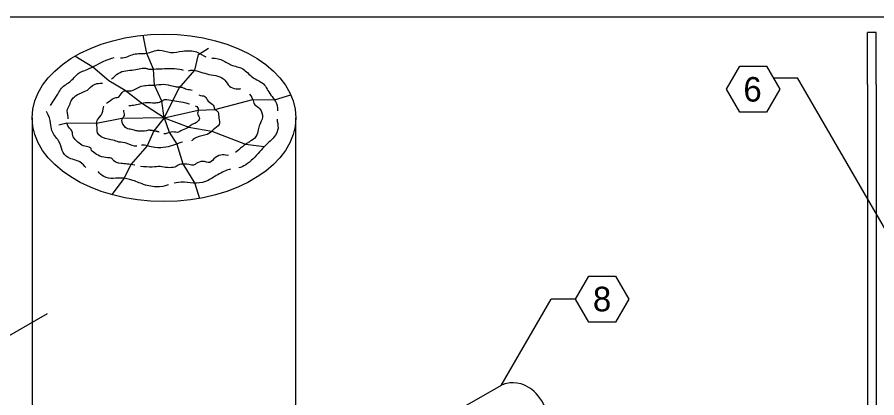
# Model space of a CAD drawing. Extents: x 99862 to 103151, y 100000 to 105076.
# Drawn here: x 100805 to 101365, y 104827 to 105076 of the extents above; entities that cross this region are included whole.
import ezdxf

# ---------------------------------------------------------------- set-up
doc = ezdxf.new("R2010")
doc.units = 0
for name, color, linetype in [('Level 1', 7, 'Continuous'), ('Level 13', 7, 'Continuous'), ('Level 15', 7, 'Continuous'), ('Level 16', 7, 'Continuous'), ('Level 20', 7, 'Continuous'), ('Level 31', 7, 'Continuous'), ('Level 41', 7, 'Continuous')]:
    doc.layers.add(name, color=color, linetype=linetype)

msp = doc.modelspace()

# ---------------------------------------------------------------- linework, layer by layer
at = {"layer": 'Level 1'}
msp.add_lwpolyline([(99862, 102999.5), (103151, 102999.5), (103151, 105075.5), (99862, 105075.5)], close=True, dxfattribs=at)
at = {"layer": 'Level 13'}
msp.add_line((101120.49, 104835.56), (101096.62, 104821.78), dxfattribs=at)
for points, degree in [([(101151.84, 104806.5), (101152.06, 104822.03), (101135.62, 104841.83), (101121.8, 104836.21), (101121.6, 104836.13)], 3), ([(101121.6, 104836.13), (101121.33, 104836), (101121.06, 104835.86), (101120.79, 104835.73)], 2)]:
    msp.add_open_spline(points, degree=degree, dxfattribs=at)
at = {"layer": 'Level 15'}
for p, q in [((101297.58, 105036.01), (101313.58, 105036.01)), ((101394.61, 104895.65), (101313.58, 105036.01)), ((101120.49, 104835.56), (101152.99, 104891.85)), ((101168.99, 104891.85), (101152.99, 104891.85))]:
    msp.add_line(p, q, dxfattribs=at)
at = {"layer": 'Level 16'}
msp.add_line((100824.93, 104882.2), (100689.17, 104803.82), dxfattribs=at)
at = {"layer": 'Level 20'}
for points in [[(101267.27, 105028.51), (101275.93, 105043.51), (101293.26, 105043.51), (101301.9, 105028.51), (101293.26, 105013.51), (101275.93, 105013.51), (101267.27, 105028.51)], [(101168.99, 104891.85), (101177.65, 104906.85), (101194.97, 104906.85), (101203.62, 104891.85), (101194.97, 104876.86), (101177.65, 104876.86), (101168.99, 104891.85)]]:
    msp.add_lwpolyline(points, dxfattribs=at)
at = {"layer": 'Level 31'}
for p, q in [((100815.22, 105009.95), (100815.22, 104646.8)), ((100986.88, 104403.51), (100986.88, 105009.95))]:
    msp.add_line(p, q, dxfattribs=at)
for points in [[(100901.05, 105009.95), (100899.62, 105020.7), (100894.76, 105031.18), (100894.16, 105041.71), (100889.71, 105051.81), (100887.47, 105063.77)], [(100901.05, 105009.95), (100910.97, 105029.15), (100921.16, 105040.87), (100923.53, 105051.12), (100929.95, 105055.37)], [(100901.05, 105009.95), (100886.29, 105019.37), (100875.61, 105027.79), (100864.97, 105034.06), (100854.58, 105042.86), (100842.86, 105050.02)], [(100901.05, 105009.95), (100923.33, 105014.84), (100934.19, 105015.31), (100958.85, 105021.82), (100972.96, 105021.75), (100983.59, 105024.9)], [(100901.05, 105009.95), (100873.62, 105009.39), (100857.12, 105006.2), (100837.8, 105006.38), (100832.44, 105005.25)], [(100901.05, 105009.95), (100894.35, 105001.44), (100889.97, 104991.71), (100879.32, 104979.57), (100874.98, 104970.67), (100866.91, 104959.94)], [(100901.05, 105009.95), (100904.45, 105000.56), (100909.35, 104992.75), (100913.15, 104979.86), (100921.13, 104967.21), (100924.05, 104957.43)], [(100901.05, 105009.95), (100917.21, 105003.88), (100932.16, 105001.33), (100954.13, 104992.76), (100966.31, 104991.23)]]:
    msp.add_lwpolyline(points, dxfattribs=at)
msp.add_ellipse((100901.05, 105009.95), major_axis=(85.83, 0), ratio=0.635085, dxfattribs=at)
for points, degree in [([(100872.65, 105049.01), (100876.22, 105048.77), (100881.15, 105052.6), (100889.55, 105051.04), (100898.09, 105055.42), (100905.15, 105051.47), (100912.88, 105053.85), (100923.12, 105053.71), (100926.35, 105050.28), (100928.16, 105049.65)], 3), ([(100827.12, 105017.92), (100831.74, 105024.73), (100833.51, 105029.87), (100840.78, 105033.54), (100845.46, 105040.21), (100851.48, 105040.85), (100864.62, 105048.68), (100868.54, 105049.19)], 3), ([(100932.11, 105048.9), (100932.59, 105048.86), (100938.72, 105048.63), (100944.01, 105043.76), (100952.9, 105042.84), (100958.08, 105035.55), (100966.66, 105033.03), (100969.58, 105024.58), (100975.43, 105019.73), (100974.86, 105014.43)], 3), ([(100866.87, 105035.29), (100868.42, 105036.4), (100871.06, 105039.43), (100875.93, 105040.86), (100881.55, 105040.93), (100886.16, 105042.3), (100889.34, 105042.52), (100890.49, 105041.42), (100895.85, 105041.85), (100901.05, 105041.96), (100907.74, 105042.39), (100912.25, 105041.33), (100913.46, 105041.07)], 3), ([(100917.01, 105040.75), (100917.54, 105040.83), (100919.85, 105041.43), (100925, 105039.77), (100929.94, 105038.04), (100936.39, 105037.45), (100940.96, 105034.86), (100943.05, 105030.04), (100948.07, 105028.46), (100950.78, 105028.94), (100950.91, 105028.96)], 3), ([(100851.17, 105027.88), (100855.59, 105033.49), (100859.53, 105032.25), (100860.95, 105032.46)], 3), ([(100838.48, 105009.19), (100838.77, 105010.58), (100837.09, 105014.96), (100839.88, 105018.07), (100840.21, 105021.94), (100845, 105025.71), (100851.17, 105027.88)], 3), ([(100863.52, 105019.53), (100865.49, 105020.69), (100868.88, 105023.72), (100872.08, 105022.68), (100873.97, 105028.5), (100879.8, 105026.61), (100884.51, 105030.53), (100888.57, 105031), (100889.47, 105031.07)], 3), ([(100889.47, 105031.07), (100891.21, 105031.19), (100894.29, 105030.97), (100900.71, 105032.28), (100907.03, 105030.48), (100909.58, 105029.97), (100912.69, 105030.18), (100915.74, 105028.21), (100918.38, 105028.42), (100919.35, 105028)], 3), ([(100878.01, 105017.88), (100878.01, 105017.88), (100879.93, 105018.07), (100884.21, 105018.79), (100888.79, 105020.06), (100892.69, 105019.84), (100894.16, 105019.44), (100897.03, 105019.92), (100900.67, 105020.96), (100901.05, 105022.42), (100906.86, 105020.91), (100911.66, 105020.69), (100916.37, 105019.38), (100917.6, 105019.01)], 3), ([(100923.77, 105024.93), (100925.13, 105024.22), (100928.38, 105024.62), (100928.87, 105020.54), (100934.18, 105018.19), (100933.08, 105015.7), (100936.93, 105014), (100936.26, 105009.74), (100938.02, 105005.44), (100932.55, 105001.99), (100930.11, 104998.79), (100921.21, 104997.56), (100919.28, 104995.12), (100918.99, 104994.85)], 3), ([(100956.67, 105025.36), (100957.83, 105023.86), (100959.44, 105020.73), (100959.49, 105018.3), (100963.84, 105016.48), (100965.91, 105010.02), (100962.9, 105005.34), (100962.4, 105002.38), (100961.57, 104997.35), (100956.6, 104994.25), (100954.92, 104993.34), (100952.57, 104991.61), (100948.71, 104988.13), (100947.57, 104987.37)], 3), ([(100860.11, 104997.46), (100857.28, 104999.69), (100857.76, 105002.01), (100857.12, 105005.7), (100856.99, 105008.43), (100861.43, 105012.63), (100861.43, 105016.61), (100861.76, 105017.48)], 3), ([(100921.38, 105017.78), (100922.84, 105017.14), (100923.66, 105015.26), (100922.25, 105012.01), (100925, 105009.78), (100922.29, 105006.44), (100918.14, 105005.31), (100917.31, 105003.61), (100912.58, 105001.98), (100909.9, 104999.8), (100905.87, 105001.49), (100902.3, 104999.33), (100900.93, 104999.47)], 3), ([(100850.16, 104977.64), (100849.03, 104978.25), (100847.25, 104981.82), (100837.56, 104983.49), (100834.32, 104988.29), (100833.33, 104995.14), (100826.46, 105000.97), (100827.82, 105007.89), (100824.49, 105014.11)], 3), ([(100890.91, 105001.91), (100887.03, 105000.71), (100882.07, 105001.6), (100878.98, 105002.68), (100875.95, 105002.69), (100872.28, 105008.76), (100876.35, 105011.22), (100874.73, 105013.9), (100874.92, 105015.02)], 3), ([(100882.01, 104979.06), (100878.19, 104979.91), (100872.36, 104979.88), (100867.6, 104981.73), (100867.6, 104983.99), (100861.54, 104983.9), (100856.73, 104985.93), (100853.09, 104989.11), (100853.82, 104989.94), (100852.72, 104990.76), (100848.21, 104991.52), (100845.07, 104993.8), (100841.14, 104997.54), (100841.78, 105001.25), (100839.52, 105002.75), (100837.99, 105005.36), (100837.85, 105006.04)], 3), ([(100974.6, 105009.16), (100974.7, 105007.3), (100976.09, 105003.27), (100972.99, 104996.92), (100967.32, 104992.69), (100959.4, 104982.96), (100952.38, 104977.63), (100949.63, 104977.35)], 3), ([(100897.78, 105000.62), (100895.38, 105001.44), (100890.91, 105001.91)], 2), ([(100883.33, 104991.38), (100881.23, 104990.95), (100876.97, 104993.86), (100871.26, 104993.85), (100868.04, 104995.6), (100864.01, 104995.82), (100860.1, 104997.46)], 3), ([(100913.1, 104994.05), (100911.64, 104993.93), (100907.89, 104991.95), (100902.27, 104990.8), (100895.65, 104989.9), (100888.5, 104992.25), (100886.39, 104992.12)], 3), ([(100942.96, 104985.49), (100941.71, 104985.33), (100939.48, 104986.42), (100934.05, 104984.57), (100931.15, 104979.61), (100926.19, 104982.5), (100921.29, 104979.83), (100919.91, 104978.55), (100916.36, 104979.86), (100910.33, 104979.87), (100908.73, 104977.53), (100903.17, 104977.28), (100898.34, 104978.43), (100893.91, 104977.72), (100888.2, 104977.86), (100885.65, 104978.29)], 3), ([(100944.24, 104976.53), (100942.8, 104976.11), (100936.43, 104973.64), (100930.01, 104968.7), (100922.15, 104966.71), (100914.26, 104968.56), (100908.91, 104967.72), (100907.6, 104967.4)], 3), ([(100903.83, 104966.26), (100903.17, 104966.02), (100898.77, 104964.19), (100888.33, 104965.79), (100880.92, 104969.53), (100872.78, 104971.19), (100866.31, 104969.81), (100860.13, 104972.18), (100858.21, 104974.8), (100858.02, 104975.01)], 3)]:
    msp.add_open_spline(points, degree=degree, dxfattribs=at)
at = {"layer": 'Level 41'}
for p, q in [((101364.79, 105065.49), (101359.17, 105065.49)), ((101359.17, 105031.74), (101359.17, 105065.49)), ((101364.79, 105031.74), (101364.79, 105065.49)), ((101359.17, 105031.74), (101359.17, 104750.04)), ((101364.79, 105031.74), (101364.79, 104750.04))]:
    msp.add_line(p, q, dxfattribs=at)

# ---------------------------------------------------------------- texts
at = {"layer": 'Level 20'}
for s, p in [('6', (101278.28, 105020.51)), ('8', (101180.29, 104883.86))]:
    msp.add_text(s, height=16, dxfattribs=at).set_placement(p)

doc.saveas('drawing.dxf')
